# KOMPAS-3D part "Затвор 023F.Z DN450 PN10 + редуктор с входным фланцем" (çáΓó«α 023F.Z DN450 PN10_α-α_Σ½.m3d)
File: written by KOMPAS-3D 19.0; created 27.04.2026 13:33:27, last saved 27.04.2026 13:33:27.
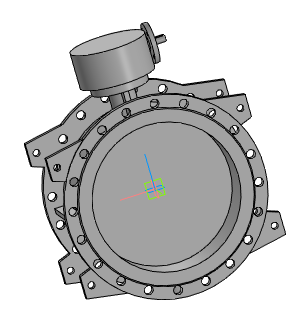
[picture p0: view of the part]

Document properties: Полное имя файла: ..\..\Затвор 023F.Z DN200-DN1600_редуктор с входным фланцем\Затвор 023F.Z DN450 PN10 + редуктор с входным фланцем.a3d

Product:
- Part/product: Затвор 023F.Z DN450 PN10 + редуктор с входным фланцем
    Масса: 222.354

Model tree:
1. Операция без истории:1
